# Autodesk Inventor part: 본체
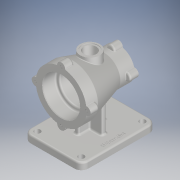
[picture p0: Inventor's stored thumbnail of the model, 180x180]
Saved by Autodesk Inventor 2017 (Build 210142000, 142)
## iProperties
Part Number: 본체
Material: 알루미늄 6061
Document SubType Name: Modeling
Designer: 7-1
Density: 2.7 g/cm^3
Appearance: 알루미늄 - 평지
Mass: 1030.22 g
Surface Area: 851.044 cm^2
Volume: 381.564 cm^3
Author: 7-1
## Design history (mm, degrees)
sketch "스케치1"
  geometry: L1 (-50, 0)-(50, 0); L2 (-50, 0)-(-50, 44); L3 (-50, 44)-(-30, 44); L4 (-30, 44)-(25, 27.5); L5 (25, 27.5)-(50, 27.5); L6 (50, 27.5)-(50, 0); 2 further points
  constraints: 12 end point, 2 perpendicular, 1 coincident, 1 horizontal, 1 midpoint, 1 parallel, 1 vertical
  dimensions: "d0" = 88 diameter of L3 L1; "d1" = 55 diameter of L5 L1; "d2" = 100 distance of L1.start L1.end; "d3" = 20 distance of L2.end L3.end; "d5" = 25 distance of L4.end L5.end
revolve "회전1" sketch "스케치1" stored, may be unused: angle "d6" = 90 deg
node "작업 평면1"
sketch "스케치2"
  geometry: L1 (65, -50)-(-65, -50); L2 (-65, -50)-(-65, 50); L3 (-65, 50)-(65, 50); L4 (65, 50)-(65, -50); 3 further points
  constraints: 8 end point, 2 midpoint, 2 parallel, 1 horizontal, 1 horizontal alignment, 1 perpendicular, 1 vertical alignment
  dimensions: "d8" = 130 distance of L1.start L1.end; "d9" = 100 distance of L1.end L2.end
extrude "돌출1" join sketch "스케치2" distance "d10" = 12; taper "d11" = 0 deg
sketch "스케치3"
  geometry: L1 (4, -25)-(-4, -25); L2 (-4, -25)-(-4, 25); L3 (-4, 25)-(4, 25); L4 (4, 25)-(4, -25); L5 (4, -25)-(-4, 25); L6 (-4, -25)-(4, 25); L7 (24, 4)-(-24, 4); L8 (-24, 4)-(-24, -4); L9 (-24, -4)-(24, -4); L10 (24, -4)-(24, 4); L11 (24, 4)-(-24, -4); L12 (-24, 4)-(24, -4); 1 further point
  constraints: 24 end point, 4 midpoint, 4 parallel, 2 horizontal, 2 perpendicular
  dimensions: "d12" = 8 distance of L2.end L3.end; "d13" = 8 distance of L9.end L7.start; "d14" = 48 distance of L8.end L9.end; "d15" = 50 distance of L3.end L1.start
extrude "돌출2" join sketch "스케치3" stored distance "d16" = 12; taper "d17" = 0 deg
sketch "스케치4"
  geometry: L1 (-50, 0)-(50, 0); L2 (-50, -44)-(-50, 44) reference; L3 (50, -27.5)-(50, 27.5) reference; L4 (-50, 0)-(-50, 32); L5 (-50, 32)-(-27, 32); L6 (-27, 32)-(-27, 26); L7 (-27, 26)-(20, 26); L8 (20, 26)-(20, 20); L9 (20, 20)-(50, 20); L10 (50, 0)-(50, 20); 2 further points
  constraints: 16 end point, 4 perpendicular, 3 midpoint, 2 horizontal, 2 point on line, 1 coincident, 1 collinear
  dimensions: "d19" = 64 diameter of L5 L1; "d20" = 52 diameter of L7 L1; "d21" = 40 diameter of L9 L1; "d22" = 23 distance of L4.end L5.end; "d23" = 47 distance of L6.end L7.end
revolve "회전2" sketch "스케치4" stored, may be unused: angle "d24" = 90 deg
node "작업 평면2"
sketch "스케치5"
  geometry: C1 r 17 at (0, 0); 1 further point
  constraints: 1 centre point, 1 coincident
  dimensions: "d26" = 34 diameter of C1
extrude "돌출3" join sketch "스케치5" stored distance "d27" = 10; taper "d28" = 0 deg
sketch "스케치6"
  geometry: C1 r 14 at (0, 0); 1 further point
  constraints: 1 centre point, 1 coincident
  dimensions: "d29" = 28 diameter of C1
extrude "돌출4" cut sketch "스케치6" distance "d30" = 1; taper "d31" = 0 deg
sketch "스케치7"
  geometry: C1 r 11 at (0, 0); 1 further point
  constraints: 1 centre point, 1 coincident
  dimensions: "d32" = 22 diameter of C1
extrude "돌출5" cut sketch "스케치7" stored distance "d33" = 1; taper "d34" = 0 deg
sketch "스케치8"
  geometry: L1 (-14, 44)-(14, 44) reference; C1 r 44 at (0, 0) reference; C2 r 7 at (0, 44); 1 further point
  constraints: 1 centre point, 1 midpoint
  dimensions: "d35" = 14 diameter of C2
extrude "돌출6" join sketch "스케치8" distance "d36" = 15; taper "d37" = 0 deg
sketch "스케치9"
  geometry: A1 r 7 centre (0, 0) between (6.978, -0.557) and (-6.978, -0.557) reference; 1 further point
hole "구멍1" sketch "스케치9" at (0, 0) diameter "d38" = 4.134; stored, may be unused: countersink angle "d42" = 90 deg, drill point angle "d44" = 118 deg; dims "d39" = 9, "d40" = 4, "d41" = 2, "d43" = 11
fillet "모깎기1" dims "d45" = 1, "d46" = 3
sketch "스케치10"
  geometry: C1 r 7 at (0, 27.5); 2 further points
  constraints: 2 vertical alignment, 1 centre point, 1 other
  dimensions: "d50" = 14 diameter of C1
extrude "돌출7" join sketch "스케치10" distance "d51" = 15; taper "d52" = 0 deg
sketch "스케치11"
  geometry: C1 r 20 at (0, -27.5) reference; A1 r 27.5 centre (0, -27.5) between (-6.943, -0.891) and (6.943, -0.891) reference; A2 r 7 centre (0, 0) between (6.943, -0.891) and (-6.943, -0.891) reference; 1 further point
hole "구멍2" sketch "스케치11" at (0, 0) diameter "d53" = 4.134; stored, may be unused: countersink angle "d57" = 90 deg, drill point angle "d59" = 118 deg; dims "d54" = 9, "d55" = 4, "d56" = 2, "d58" = 11
fillet "모깎기2" dims "d60" = 1, "d61" = 3
fillet "모깎기3" dims "d65" = 12
sketch "스케치12"
  geometry: L1 (65, 38)-(65, -38) reference; L2 (53, -50)-(-53, -50) reference; L3 (-65, -38)-(-65, 38) reference; L4 (-53, 50)-(53, 50) reference; A1 r 12 centre (53, 38) between (65, 38) and (53, 50) reference; A2 r 12 centre (53, -38) between (53, -50) and (65, -38) reference; A3 r 12 centre (-53, -38) between (-65, -38) and (-53, -50) reference; A4 r 12 centre (-53, 38) between (-53, 50) and (-65, 38) reference; 1 further point
hole "구멍3" sketch "스케치12" at (53, -38), (53, 38), (-53, 38), (-53, -38) diameter "d66" = 10; stored, may be unused: countersink angle "d70" = 90 deg, drill point angle "d72" = 118 deg; dims "d67" = 9, "d68" = 4, "d69" = 2, "d71" = 11
node "작업 평면3"
sketch "스케치13"
  geometry: L1 (-53, -50)-(53, -50) reference; 2 further points
  constraints: 1 vertical alignment, 1 other
  dimensions: "d74" = 10 distance from line of L1 point (0, -40)
feature "엠보싱1" sketch "스케치13" dims "d0" = 88, "d1" = 55, "d2" = 100, "d3" = 20, "d5" = 25, "d12" = 8, "d15" = 50, "d75" = 0.5, "d76" = 0
chamfer "모따기1" distance "d77" = 1; stored, may be unused: second distance "d78" = 2, angle "d79" = 45 deg
fillet "모깎기4" dims "d80" = 3
fillet "모깎기5" dims "d81" = 1
fillet "모깎기6" dims "d82" = 3
fillet "모깎기7" dims "d83" = 3
fillet "모깎기8" dims "d84" = 3
node "솔리드1"
pattern_circular "원형 패턴1" dims angle "d48" = 360 deg
pattern_circular "원형 패턴2" dims angle "d63" = 360 deg
node "투영된 루프1"
node "투영된 루프2"
other parameters: "d7" = -82, "d25" = 45, "d73" = 5
